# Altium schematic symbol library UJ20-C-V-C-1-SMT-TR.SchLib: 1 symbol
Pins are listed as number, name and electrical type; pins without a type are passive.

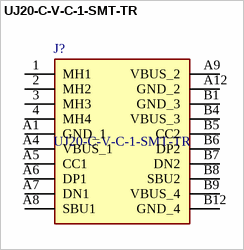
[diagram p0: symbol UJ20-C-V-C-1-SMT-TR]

## UJ20-C-V-C-1-SMT-TR
designator J?
USB Connectors USB Jack 2.0, Type-C, Vertical, Copper Alloy, Surface Mount, 6.5H, T&R; Manufacturer_Name: Same Sky; Geometry.Height: 6.65mm
footprint UJ20CVC1SMTTR
pins: 1 MH1, 2 MH2, 3 MH3, 4 MH4, A1 GND_1, A4 VBUS_1, A5 CC1, A6 DP1, A7 DN1, A8 SBU1, A9 VBUS_2, A12 GND_2, B1 GND_3, B4 VBUS_3, B5 CC2, B6 DP2, B7 DN2, B8 SBU2, B9 VBUS_4, B12 GND_4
